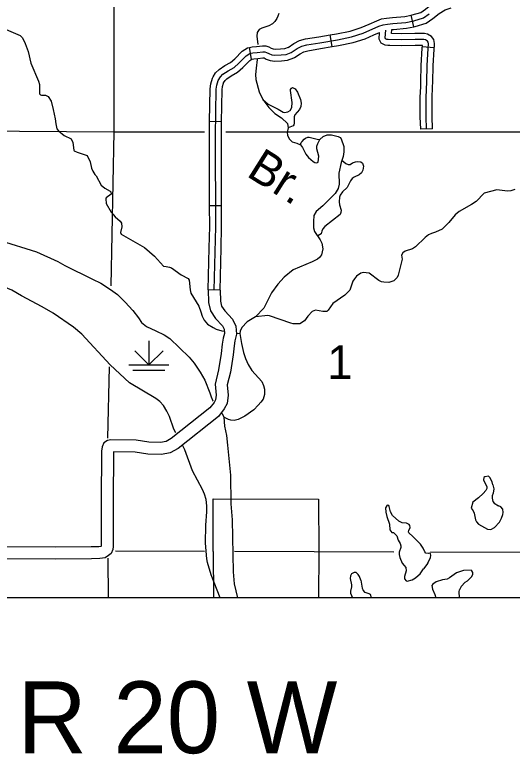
# Model space of a CAD drawing. Extents: x 1374139 to 1377472, y 1168351 to 1170484.
# Drawn here: x 1375570.5 to 1375695.3, y 1168614.5 to 1168800 of the extents above; entities that cross this region are included whole.
import ezdxf

# ---------------------------------------------------------------- set-up
doc = ezdxf.new("R2010")
doc.units = 0
doc.layers.add('26', color=7, linetype='Continuous')
doc.layers.add('Default', color=7, linetype='Continuous')

msp = doc.modelspace()

# ---------------------------------------------------------------- linework, layer by layer
at = {"layer": '26'}
msp.add_lwpolyline([(1375090, 1169579.43), (1376597.43, 1169579.43), (1376597.43, 1168653.79), (1375090, 1168653.79)], close=True, dxfattribs=at)
at = {"layer": 'Default'}
for p, q in [((1375670.59, 1168796.95), (1375669.97, 1168799.88)), ((1375650.15, 1168791.98), (1375649.65, 1168794.94)), ((1375629.87, 1168788.82), (1375629.39, 1168791.78)), ((1375675.74, 1168791.65), (1375672.75, 1168791.9)), ((1375622.39, 1168773.15), (1375619.4, 1168773.19)), ((1375675.34, 1168771.33), (1375672.34, 1168771.24)), ((1375622.4, 1168752.05), (1375619.4, 1168752.04)), ((1375622.05, 1168730.9), (1375619.05, 1168730.97)), ((1375604.16, 1168718.17), (1375604.16, 1168712.17)), ((1375604.16, 1168712.17), (1375600.63, 1168715.71)), ((1375604.16, 1168712.17), (1375607.7, 1168715.71)), ((1375599.16, 1168712.17), (1375609.16, 1168712.17)), ((1375600.16, 1168710.81), (1375608.16, 1168710.81))]:
    msp.add_line(p, q, dxfattribs=at)
for points in [[(1375594.95, 1169406.38), (1375595.34, 1168770.63)], [(1375669.97, 1168799.88), (1375670.24, 1168799.94), (1375672.42, 1168800.57), (1375673.54, 1168801.37), (1375675.27, 1168802.79), (1375677.31, 1168803.94), (1375679.12, 1168804.52)], [(1375636.74, 1168800.27), (1375636.52, 1168799.62), (1375636.27, 1168799.05), (1375635.75, 1168798.28), (1375635.13, 1168797.66), (1375634.28, 1168797.18), (1375632.49, 1168796.63), (1375631.82, 1168796.25), (1375631.3, 1168795.48), (1375631.25, 1168794.61), (1375631.46, 1168792.49)], [(1375670.59, 1168796.95), (1375670.97, 1168797.03), (1375673.75, 1168797.83), (1375675.37, 1168798.99), (1375676.97, 1168800.31), (1375678.51, 1168801.18), (1375680.03, 1168801.67)], [(1375620.55, 1168730.93), (1375620.91, 1168746.82), (1375620.85, 1168769.59), (1375621.01, 1168781.27), (1375621.17, 1168782.31), (1375621.5, 1168783.45), (1375622.08, 1168784.43), (1375622.74, 1168785.05), (1375624.01, 1168785.93), (1375625.51, 1168786.78), (1375626.71, 1168787.86), (1375628.54, 1168789.69), (1375629.45, 1168790.27), (1375630.27, 1168790.4), (1375631.34, 1168790.53), (1375632.71, 1168790.66), (1375633.27, 1168790.66), (1375633.67, 1168790.52), (1375634.22, 1168790.23), (1375634.97, 1168789.94), (1375635.78, 1168789.84), (1375637.32, 1168789.9), (1375638.59, 1168790.03), (1375639.83, 1168790.49), (1375641.33, 1168791.47), (1375642.5, 1168792.12), (1375643.74, 1168792.42), (1375647, 1168792.97), (1375651.47, 1168793.72), (1375655.02, 1168794.44), (1375657.92, 1168795.35), (1375661.87, 1168797.08), (1375662.91, 1168797.47), (1375663.99, 1168797.64), (1375665.39, 1168797.8), (1375668.59, 1168798.06), (1375670.61, 1168798.48), (1375673.09, 1168799.2), (1375674.46, 1168800.18)], [(1375659.43, 1168797.65), (1375661.3, 1168798.47), (1375662.53, 1168798.93), (1375663.79, 1168799.12), (1375665.24, 1168799.29), (1375668.37, 1168799.55), (1375669.97, 1168799.88)], [(1375649.65, 1168794.94), (1375651.2, 1168795.2), (1375654.65, 1168795.89), (1375657.4, 1168796.76), (1375659.43, 1168797.65)], [(1375665.08, 1168796.25), (1375665.54, 1168796.31), (1375668.8, 1168796.57), (1375670.59, 1168796.95)], [(1375568.34, 1168796.25), (1375571.84, 1168794.77), (1375572.41, 1168794.19), (1375573.15, 1168792.74), (1375573.84, 1168790.75), (1375574.55, 1168787.86), (1375576.48, 1168783.33), (1375576.7, 1168782.45), (1375576.74, 1168780.15), (1375576.93, 1168779.89), (1375577.21, 1168779.78), (1375578.19, 1168779.82), (1375578.88, 1168779.5), (1375579.65, 1168778.31), (1375580.18, 1168776.18), (1375580.64, 1168773.84), (1375580.77, 1168772.6), (1375581.1, 1168771.36), (1375581.46, 1168770.83), (1375582.9, 1168769.68), (1375584.68, 1168768.86), (1375585.07, 1168767.95), (1375585.34, 1168765.99), (1375585.44, 1168765.87), (1375586.17, 1168765.47), (1375588.65, 1168764.65), (1375589.43, 1168763.06), (1375589.77, 1168761.54), (1375590.05, 1168760.75), (1375590.63, 1168759.9), (1375590.96, 1168759.59), (1375592.2, 1168757.25), (1375593.13, 1168756.51), (1375594.43, 1168755.76), (1375594.62, 1168755.54), (1375594.71, 1168755.02), (1375593.46, 1168754.03), (1375593.34, 1168753.8), (1375593.47, 1168752.6), (1375594.66, 1168750.49), (1375595.73, 1168749.29), (1375596.92, 1168748.19), (1375597.25, 1168747.74), (1375597.34, 1168746.8), (1375597.01, 1168745.39), (1375597.2, 1168744.93), (1375603.07, 1168741.64), (1375605.58, 1168739.42), (1375607.8, 1168736.9), (1375608.52, 1168736.81)], [(1375639.08, 1168791.8), (1375640.55, 1168792.75), (1375641.95, 1168793.53), (1375643.44, 1168793.89), (1375646.75, 1168794.45), (1375649.65, 1168794.94)], [(1375650.15, 1168791.98), (1375651.74, 1168792.25), (1375655.4, 1168792.98), (1375658.45, 1168793.95), (1375660.63, 1168794.9)], [(1375660.63, 1168794.9), (1375662.03, 1168795.51)], [(1375664.61, 1168792.26), (1375664.08, 1168792.27), (1375663.4, 1168792.33), (1375662.4, 1168792.85), (1375661.93, 1168793.88), (1375662.03, 1168795.51)], [(1375673.84, 1168771.28), (1375673.74, 1168774.42), (1375673.71, 1168778.22), (1375673.75, 1168779.21), (1375673.89, 1168783.19), (1375673.96, 1168787.21), (1375674.22, 1168791.49), (1375674.32, 1168792.69), (1375674.23, 1168793.12), (1375674.04, 1168793.38), (1375673.52, 1168793.7), (1375673.13, 1168793.77), (1375670.92, 1168793.76), (1375667.43, 1168793.7), (1375664.16, 1168793.77), (1375663.83, 1168793.8), (1375663.55, 1168793.94), (1375663.45, 1168794.16), (1375663.57, 1168796.1)], [(1375665.02, 1168795.25), (1375665.08, 1168796.25)], [(1375675.79, 1168792.26), (1375675.83, 1168792.79), (1375675.64, 1168793.73), (1375675.08, 1168794.5), (1375674.07, 1168795.12), (1375673.26, 1168795.27), (1375670.9, 1168795.26), (1375667.43, 1168795.2), (1375665.02, 1168795.25)], [(1375620.32, 1168784.41), (1375620.9, 1168785.38), (1375621.79, 1168786.22), (1375623.21, 1168787.21), (1375624.63, 1168788.01), (1375625.68, 1168788.95), (1375627.59, 1168790.86), (1375628.91, 1168791.7), (1375629.39, 1168791.78)], [(1375629.39, 1168791.78), (1375630.06, 1168791.89), (1375631.18, 1168792.02), (1375632.64, 1168792.16), (1375633.52, 1168792.16), (1375634.27, 1168791.9), (1375634.85, 1168791.6), (1375635.34, 1168791.4), (1375635.84, 1168791.34), (1375637.21, 1168791.4), (1375638.25, 1168791.51), (1375639.15, 1168791.84), (1375639.08, 1168791.8)], [(1375640.72, 1168789.28), (1375642.1, 1168790.18), (1375643.05, 1168790.71), (1375644.04, 1168790.95), (1375647.25, 1168791.49), (1375650.15, 1168791.98)], [(1375672.78, 1168792.27), (1375670.94, 1168792.26), (1375667.43, 1168792.2), (1375664.61, 1168792.26)], [(1375672.34, 1168781.89), (1375672.39, 1168783.23), (1375672.46, 1168787.27), (1375672.72, 1168791.6), (1375672.78, 1168792.27)], [(1375675.34, 1168781.79), (1375675.39, 1168783.15), (1375675.46, 1168787.15), (1375675.71, 1168791.38), (1375675.79, 1168792.26)], [(1375629.87, 1168788.82), (1375630.48, 1168788.92), (1375631.51, 1168789.04), (1375632.78, 1168789.16), (1375633.01, 1168789.16), (1375633.06, 1168789.15), (1375633.59, 1168788.86), (1375634.6, 1168788.47), (1375635.73, 1168788.33), (1375637.43, 1168788.41), (1375638.93, 1168788.56), (1375640.51, 1168789.14), (1375640.72, 1168789.28)], [(1375622.89, 1168782.87), (1375623.27, 1168783.49), (1375623.69, 1168783.89), (1375624.81, 1168784.66), (1375626.39, 1168785.56), (1375627.74, 1168786.77), (1375629.49, 1168788.51), (1375630, 1168788.84), (1375629.87, 1168788.82)], [(1375631.31, 1168788.75), (1375631.03, 1168786.54), (1375630.92, 1168785.01), (1375631, 1168783.71), (1375631.81, 1168780.62), (1375632.7, 1168778.74), (1375634.21, 1168776.73), (1375635.79, 1168775.24), (1375637.42, 1168774.1), (1375638.89, 1168772.71), (1375639.06, 1168771.63), (1375638.87, 1168770.46), (1375638.91, 1168769.78), (1375639.31, 1168768.88), (1375640.13, 1168768.1), (1375641.28, 1168767.77), (1375642.19, 1168767.37), (1375642.66, 1168766.66), (1375643.53, 1168764.99), (1375644.19, 1168764.21), (1375645.33, 1168763.13)], [(1375619.4, 1168773.19), (1375619.51, 1168781.4), (1375619.7, 1168782.64), (1375620.11, 1168784.06), (1375620.32, 1168784.41)], [(1375622.39, 1168773.15), (1375622.51, 1168781.14), (1375622.64, 1168781.99), (1375622.89, 1168782.85), (1375622.89, 1168782.87)], [(1375632.7, 1168778.74), (1375634.11, 1168777.59), (1375636.62, 1168776.32), (1375637.86, 1168775.55), (1375638.16, 1168775.48), (1375639.04, 1168775.62), (1375639.63, 1168776), (1375639.99, 1168776.75), (1375640.1, 1168777.95), (1375639.65, 1168780.95), (1375639.7, 1168781.2), (1375639.91, 1168781.58), (1375640.17, 1168781.73), (1375640.84, 1168781.4), (1375641.44, 1168780.56), (1375642.16, 1168778.75), (1375642.35, 1168777.81), (1375642.27, 1168776.98), (1375641.97, 1168776.19), (1375640.74, 1168774.9), (1375640.59, 1168774.39), (1375640.64, 1168772.61), (1375640.54, 1168772.33), (1375640.37, 1168772.08), (1375639.06, 1168771.63)], [(1375672.34, 1168771.24), (1375672.24, 1168774.39), (1375672.21, 1168778.24), (1375672.25, 1168779.27), (1375672.34, 1168781.89)], [(1375675.34, 1168771.33), (1375675.24, 1168774.45), (1375675.21, 1168778.2), (1375675.25, 1168779.16), (1375675.34, 1168781.79)], [(1375619.37, 1168762.6), (1375619.35, 1168769.6), (1375619.4, 1168773.19)], [(1375622.37, 1168762.61), (1375622.35, 1168769.58), (1375622.39, 1168773.15)], [(1375488.68, 1168771.37), (1375595.34, 1168770.63), (1375618.13, 1168770.62)], [(1375595.34, 1168770.63), (1375594.57, 1168732.03)], [(1375623.44, 1168770.62), (1375700.37, 1168770.59)], [(1375645.33, 1168763.13), (1375645.76, 1168762.88), (1375646.28, 1168762.84), (1375646.66, 1168762.98), (1375646.78, 1168764.47), (1375646.25, 1168766.33), (1375646.32, 1168767.03), (1375646.54, 1168767.72), (1375647.05, 1168768.71), (1375647.84, 1168769.44), (1375648.86, 1168769.88), (1375649.95, 1168769.85), (1375651.65, 1168769.47), (1375652.12, 1168769.16), (1375652.37, 1168768.82), (1375653.06, 1168766.92), (1375653.09, 1168765.59), (1375652.88, 1168764.4), (1375652.38, 1168762.93), (1375651.84, 1168760.26), (1375651.87, 1168757.47), (1375651.66, 1168756.39), (1375650.87, 1168755.14), (1375647.81, 1168752.02), (1375646.11, 1168750.61), (1375645.55, 1168749.59), (1375645.45, 1168748.15), (1375645.47, 1168746.5), (1375645.71, 1168745.6), (1375647.14, 1168743.51), (1375647.54, 1168742.66), (1375647.82, 1168741.3), (1375647.42, 1168739.79), (1375646.97, 1168739.09), (1375646.46, 1168738.66), (1375645.14, 1168738), (1375640.39, 1168736.04), (1375638.12, 1168734.14), (1375636.52, 1168732.45), (1375634.89, 1168730.25), (1375633.01, 1168726.41), (1375630.9, 1168724.25), (1375628.8, 1168722.93), (1375627.49, 1168721.51), (1375627.07, 1168720.62), (1375626.99, 1168720.04), (1375627.39, 1168717.5), (1375627.93, 1168715.24), (1375628.4, 1168713.75), (1375629.04, 1168712.28), (1375629.96, 1168710.76), (1375632.45, 1168708.03), (1375632.89, 1168707.02), (1375633.16, 1168706.06), (1375633.19, 1168704.72), (1375632.82, 1168703.6), (1375632.26, 1168702.81), (1375631.56, 1168702.03), (1375630.49, 1168700.92), (1375628.21, 1168699.3), (1375626.55, 1168698.47), (1375625.55, 1168698.25), (1375624.71, 1168698.31), (1375624.09, 1168698.47), (1375622.97, 1168699.07)], [(1375642.19, 1168767.37), (1375642.35, 1168767.94), (1375642.65, 1168768.16), (1375643.11, 1168768.78), (1375643.46, 1168769.05), (1375644, 1168769.24), (1375644.4, 1168769.25), (1375646.39, 1168768.78), (1375647.05, 1168768.71)], [(1375652.58, 1168763.51), (1375653.57, 1168762.63), (1375654.19, 1168762.41), (1375654.63, 1168762.4), (1375655.26, 1168762.84), (1375655.97, 1168763.09), (1375656.49, 1168763.17), (1375657.36, 1168763.05), (1375657.72, 1168762.72), (1375657.96, 1168762.02), (1375657.79, 1168760.97), (1375657.46, 1168760.3), (1375656.94, 1168759.81), (1375655.63, 1168759.23), (1375655.18, 1168758.88), (1375654.75, 1168758.35), (1375653.93, 1168756.68), (1375652.76, 1168755.57), (1375652.16, 1168754.69), (1375651.96, 1168754.21), (1375651.92, 1168753.08), (1375651.98, 1168752.28), (1375652.4, 1168750.97), (1375652.35, 1168750.36), (1375652.16, 1168749.9), (1375648.32, 1168746.89), (1375647.81, 1168746.3), (1375647.53, 1168745.69), (1375647.36, 1168745.04), (1375646.5, 1168744.54)], [(1375619.4, 1168752.04), (1375619.37, 1168762.6)], [(1375622.4, 1168752.05), (1375622.37, 1168762.61)], [(1375695.97, 1168756.17), (1375694.96, 1168755.79), (1375694.1, 1168755.71), (1375691.47, 1168756.04), (1375688.29, 1168755.26), (1375686.27, 1168753.14), (1375685.12, 1168752.35), (1375681.99, 1168750.65), (1375681.01, 1168749.78), (1375679.4, 1168747.86), (1375677.7, 1168746.23), (1375676.06, 1168745.41), (1375675.06, 1168745.14), (1375674.31, 1168744.78), (1375673.45, 1168744.12), (1375671.07, 1168741.77), (1375670.26, 1168741.23)], [(1375619.29, 1168741.52), (1375619.41, 1168746.83), (1375619.4, 1168752.04)], [(1375622.29, 1168741.46), (1375622.41, 1168746.8), (1375622.4, 1168752.05)], [(1375566.8, 1168743.4), (1375575.93, 1168740.55), (1375581.35, 1168738.06), (1375583.04, 1168737.1), (1375590.02, 1168733.7), (1375592.07, 1168732.64), (1375594.53, 1168731.1), (1375596.24, 1168729.83), (1375598.21, 1168727.9), (1375600.12, 1168725.78), (1375601.57, 1168723.95), (1375602.34, 1168722.8), (1375603.52, 1168721.77), (1375605.91, 1168720.74), (1375607.97, 1168719.73), (1375609.42, 1168718.78)], [(1375619.05, 1168730.97), (1375619.29, 1168741.52)], [(1375622.05, 1168730.9), (1375622.29, 1168741.46)], [(1375670.26, 1168741.23), (1375668.47, 1168740.71), (1375667.88, 1168740.29), (1375667.56, 1168739.72), (1375667.66, 1168738.72), (1375666.71, 1168734.64), (1375666.44, 1168734.11), (1375665.58, 1168733.27), (1375664.33, 1168732.82), (1375663.09, 1168732.89), (1375662.51, 1168733.01), (1375661.88, 1168733.3), (1375659.39, 1168735.16), (1375657.93, 1168735.33), (1375657.35, 1168735.13), (1375656.27, 1168734.44), (1375655.73, 1168733.77), (1375655.34, 1168733.14), (1375654.6, 1168730.91), (1375653.33, 1168729.66), (1375650.3, 1168727.54), (1375649.1, 1168725.86), (1375648.77, 1168725.59), (1375647.83, 1168725.53), (1375645.98, 1168725.88), (1375645.15, 1168725.58), (1375644.06, 1168724.35), (1375643.21, 1168723.21), (1375642.01, 1168722.45), (1375640.37, 1168722.45), (1375639.8, 1168722.6), (1375634.4, 1168724.51), (1375634, 1168724.54), (1375630.9, 1168724.25)], [(1375585.2, 1168721.64), (1375580.1, 1168725.12), (1375577.38, 1168726.74), (1375572.23, 1168729.48), (1375569.75, 1168730.91), (1375561.24, 1168734.41), (1375558.61, 1168735.05), (1375555.4, 1168735.41), (1375553.97, 1168735.68), (1375549.91, 1168735.52), (1375547.18, 1168735.17), (1375543.86, 1168734.56), (1375539.7, 1168733.5), (1375538.56, 1168733.05), (1375537.33, 1168732.3), (1375536, 1168731.28), (1375534.5, 1168729.62), (1375532.08, 1168723.94), (1375530.84, 1168719.35), (1375530.41, 1168716.57), (1375529.72, 1168709.47), (1375530.04, 1168707.27)], [(1375608.52, 1168736.81), (1375609.32, 1168736.7), (1375609.81, 1168736.51), (1375612.25, 1168734.77), (1375613.99, 1168733.87), (1375614.22, 1168733.43), (1375614.51, 1168730.95), (1375614.71, 1168730.13), (1375616.67, 1168726.93), (1375617.2, 1168725.5), (1375617.49, 1168724.36)], [(1375622.05, 1168730.9), (1375622.14, 1168728.18), (1375622.41, 1168726.9), (1375623.23, 1168725.72), (1375625.13, 1168723.66), (1375625.94, 1168721.9), (1375626.14, 1168719.83), (1375625.74, 1168718.22), (1375625.51, 1168716.96), (1375625.26, 1168714.66), (1375624.59, 1168710.34), (1375623.82, 1168707.13), (1375624.02, 1168704.57), (1375623.82, 1168702.5), (1375623.06, 1168701.11), (1375621.62, 1168699.26), (1375611.47, 1168691.23), (1375609.49, 1168690.08), (1375607.31, 1168689.71), (1375603.89, 1168689.82), (1375600.74, 1168690.32), (1375595.3, 1168690.36), (1375595.18, 1168677.87), (1375595.2, 1168666.64), (1375595.11, 1168665.85), (1375594.67, 1168664.9), (1375594.02, 1168664.35), (1375593.17, 1168663.8), (1375591.85, 1168663.58), (1375589.72, 1168663.56), (1375580.84, 1168663.46), (1375561.77, 1168663.56)], [(1375619.05, 1168730.97), (1375619.15, 1168727.83), (1375619.59, 1168725.69), (1375620.89, 1168723.84), (1375622.61, 1168721.97), (1375623.01, 1168721.11), (1375623.11, 1168720.06), (1375622.81, 1168718.85), (1375622.54, 1168717.39), (1375622.28, 1168715.05), (1375621.64, 1168710.92), (1375620.8, 1168707.37), (1375621.01, 1168704.6), (1375620.89, 1168703.4), (1375620.55, 1168702.77), (1375619.48, 1168701.39), (1375609.78, 1168693.71), (1375608.45, 1168692.95), (1375607.1, 1168692.71), (1375604.18, 1168692.81), (1375600.99, 1168693.31), (1375594.64, 1168693.37), (1375593.74, 1168693.2), (1375592.82, 1168692.65), (1375592.41, 1168691.61), (1375592.3, 1168690.55), (1375592.18, 1168677.88), (1375592.2, 1168666.8), (1375592.2, 1168666.75), (1375592.06, 1168666.66), (1375591.58, 1168666.58), (1375589.68, 1168666.56), (1375580.83, 1168666.46), (1375561.8, 1168666.56)], [(1375617.49, 1168724.36), (1375618.04, 1168723.41), (1375618.86, 1168722.41), (1375620.26, 1168721.56), (1375621.05, 1168721.16), (1375622.48, 1168720.73), (1375622.87, 1168720.66)], [(1375610.88, 1168695.14), (1375610.44, 1168696.07), (1375609.29, 1168699.21), (1375608.67, 1168700.54), (1375607.82, 1168701.99), (1375606.87, 1168702.97), (1375605.91, 1168703.76), (1375599.27, 1168707.65), (1375594.42, 1168712.15), (1375587.33, 1168719.88), (1375585.2, 1168721.64)], [(1375609.42, 1168718.78), (1375614.29, 1168714.13), (1375615.55, 1168712.61), (1375617.03, 1168710.38), (1375618.22, 1168708.36), (1375619.48, 1168705.12), (1375619.76, 1168704.13), (1375620.21, 1168703.15), (1375620.24, 1168703.11)], [(1375626.4, 1168720.14), (1375626.99, 1168720.04)], [(1375594.16, 1168711.64), (1375593.81, 1168693.78)], [(1375622.49, 1168700.08), (1375622.55, 1168699.98), (1375622.97, 1168699.07), (1375623.15, 1168696.84), (1375623.61, 1168694.45), (1375623.91, 1168692.03), (1375624.65, 1168684.5), (1375624.69, 1168677.36), (1375625.03, 1168673.31), (1375625.26, 1168660.27), (1375625.59, 1168657.29), (1375626.42, 1168653.79)], [(1375622.04, 1168653.79), (1375619.78, 1168659.48), (1375618.88, 1168662.58), (1375618.66, 1168663.56), (1375618.34, 1168667.45), (1375618.47, 1168671.97), (1375618.7, 1168675.32), (1375618.69, 1168676.85), (1375618.49, 1168678.37), (1375618.13, 1168679.78), (1375617.62, 1168680.9), (1375615.09, 1168685.57), (1375613.17, 1168690.88), (1375612.7, 1168691.91)], [(1375690.42, 1168682.13), (1375690.3, 1168682.87), (1375689.69, 1168683.96), (1375689.39, 1168684.27), (1375688.43, 1168684.13), (1375688.21, 1168683.96), (1375688.13, 1168683.32), (1375688.93, 1168681.55), (1375688.9, 1168681.21), (1375688.66, 1168680.66), (1375688.04, 1168679.88), (1375686.86, 1168678.83), (1375685.43, 1168677.75), (1375684.99, 1168676.27), (1375685.48, 1168675.54), (1375685.72, 1168674.97), (1375686.08, 1168673.31), (1375686.33, 1168672.82), (1375686.87, 1168672.21), (1375689.08, 1168670.94), (1375689.92, 1168670.88), (1375690.89, 1168671.4), (1375692.09, 1168672.76), (1375692.63, 1168673.75), (1375692.95, 1168674.64), (1375693.05, 1168675.17), (1375692.97, 1168675.97), (1375692.48, 1168676.54), (1375691.89, 1168676.79)], [(1375690.42, 1168682.13), (1375690.66, 1168681.06), (1375690.53, 1168679.97), (1375690.3, 1168679.3), (1375690.28, 1168678.71), (1375690.48, 1168677.9), (1375690.77, 1168677.5), (1375691.89, 1168676.79)], [(1375620.31, 1168665.39), (1375620.25, 1168678.59), (1375646.7, 1168678.5), (1375646.76, 1168665.29), (1375646.72, 1168653.79)], [(1375674.11, 1168662.44), (1375674.79, 1168663.84), (1375674.9, 1168664.33), (1375674.83, 1168664.83), (1375674.59, 1168664.96), (1375674.27, 1168664.89), (1375673.61, 1168664.98), (1375673.36, 1168665.25), (1375672.98, 1168666.23), (1375672.29, 1168667.17), (1375670.38, 1168669.17), (1375669.4, 1168670.07), (1375669.31, 1168670.33), (1375669.34, 1168670.63), (1375669.73, 1168671.38), (1375669.63, 1168671.86), (1375669.49, 1168672.1), (1375669.16, 1168672.35), (1375668.8, 1168672.46), (1375667.72, 1168672.54), (1375666.83, 1168672.98), (1375665.23, 1168674.4), (1375664.81, 1168675.28), (1375664.47, 1168676.65), (1375664.35, 1168676.89), (1375663.97, 1168676.98), (1375663.52, 1168676.29), (1375663.57, 1168675.24), (1375663.82, 1168674.13), (1375664.51, 1168672.2), (1375664.58, 1168670.81), (1375665.08, 1168670.1), (1375665.56, 1168670.12), (1375666.38, 1168669.29), (1375666.7, 1168668.24), (1375667.21, 1168667.37), (1375667.38, 1168666.77), (1375667.37, 1168666.37), (1375666.94, 1168665.17), (1375666.97, 1168664.61), (1375667.15, 1168663.83), (1375667.69, 1168662.44), (1375668.22, 1168661.89), (1375668.58, 1168661.34), (1375668.68, 1168660.56), (1375668.27, 1168659.07), (1375668.31, 1168658.5), (1375668.66, 1168658.05), (1375668.96, 1168657.92), (1375670.17, 1168658.25), (1375671.08, 1168658.77), (1375671.75, 1168659.33), (1375672.22, 1168659.81), (1375673.07, 1168660.99)], [(1375618.11, 1168665.39), (1375595.75, 1168665.47)], [(1375620.31, 1168665.39), (1375620.36, 1168653.79)], [(1375665.64, 1168665.23), (1375625.65, 1168665.37)], [(1375699.68, 1168665.11), (1375674.82, 1168665.2)], [(1375593.87, 1168663.67), (1375593.91, 1168653.79)], [(1375674.11, 1168662.44), (1375673.07, 1168660.99)], [(1375657.31, 1168658.19), (1375657.01, 1168659.11), (1375656.68, 1168659.6), (1375656.13, 1168660.09), (1375655.63, 1168660.12), (1375654.98, 1168659.76), (1375654.71, 1168659.29), (1375654.68, 1168658.63), (1375655, 1168657.01), (1375655, 1168656.47), (1375654.7, 1168655.44), (1375654.72, 1168654.94), (1375654.95, 1168654.32), (1375655.26, 1168653.79)], [(1375683.53, 1168657.64), (1375684.1, 1168658.03), (1375685.16, 1168659.06), (1375685.4, 1168659.67), (1375685.41, 1168660.09), (1375685.18, 1168660.55), (1375684.97, 1168660.7), (1375683.08, 1168660.59), (1375681.29, 1168659.99), (1375679.6, 1168658.74), (1375679.01, 1168658.43), (1375677.79, 1168658.26), (1375676.19, 1168657.74), (1375675.38, 1168657.19), (1375675.15, 1168656.87), (1375675.29, 1168655.93), (1375675.87, 1168654.62), (1375676.12, 1168653.79)], [(1375657.31, 1168658.19), (1375657.7, 1168656.21), (1375657.94, 1168655.64)], [(1375683.53, 1168657.64), (1375682.46, 1168656.57), (1375682.1, 1168655.75)], [(1375659.98, 1168653.79), (1375659.77, 1168654.56), (1375659.42, 1168654.77), (1375658.39, 1168655.09), (1375657.94, 1168655.64)], [(1375682.12, 1168653.79), (1375682.11, 1168653.83), (1375682.01, 1168655.25), (1375682.1, 1168655.75)]]:
    msp.add_lwpolyline(points, dxfattribs=at)

# ---------------------------------------------------------------- texts
msp.add_text('Br.', height=8.448, rotation=327.7936, dxfattribs=at).set_placement((1375628.35, 1168759.69))
for s, height, p in [('1', 8.45, (1375648.92, 1168708.62)), ('R 20 W', 18, (1375571.18, 1168614.79))]:
    msp.add_text(s, height=height, dxfattribs=at).set_placement(p)

doc.saveas('drawing.dxf')
